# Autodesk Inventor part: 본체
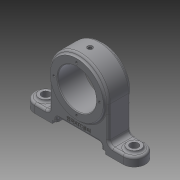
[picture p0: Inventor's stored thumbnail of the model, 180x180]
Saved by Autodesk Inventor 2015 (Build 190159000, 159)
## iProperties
Created: 2019-05
Part Number: 본체
Material: 알루미늄 6061
Document SubType Name: Modeling
Designer: now
Density: 2.7 g/cm^3
Appearance: 기본값
Mass: 456.09 g
Surface Area: 318.797 cm^2
Volume: 168.922 cm^3
Author: now
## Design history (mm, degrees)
sketch "스케치1"
  geometry: L1 (-60, -15)-(60, -15); L2 (60, -15)-(60, 15); L3 (60, 15)-(-60, 15); L4 (-60, 15)-(-60, -15); L5 (-60, -15)-(60, 15); L6 (60, -15)-(-60, 15); 1 further point
  constraints: 12 end point, 2 midpoint, 2 parallel, 1 horizontal, 1 perpendicular
  dimensions: "d0" = 120 distance of L2.end L3.end; "d1" = 30 distance of L1.end L2.end
extrude "돌출1" new body sketch "스케치1" distance "d2" = 12; taper "d3" = 0 deg
sketch "스케치2"
  geometry: L1 (60, -15)-(60, 15) reference; L2 (-60, 15)-(-60, -15) reference; 3 further points
  constraints: 2 midpoint, 2 vertical alignment, 4 other
extrude "돌출2" join sketch "스케치2" distance "d4" = 12; taper "d5" = 0 deg
sketch "스케치3"
  geometry: C1 r 9 at (-60, 0); C2 r 9 at (60, 0); A1 r 15 centre (60, 0) between (60, -15) and (60, 15) reference; A2 r 15 centre (-60, 0) between (-60, 15) and (-60, -15) reference; 1 further point
  constraints: 2 centre point, 2 coincident
  dimensions: "d6" = 18 diameter of C2; "d7" = 18 diameter of C1
extrude "돌출3" join sketch "스케치3" distance "d8" = 3; taper "d9" = 0 deg
sketch "스케치4"
  geometry: C1 r 9 at (0, 0) reference; 1 further point
hole "구멍1" sketch "스케치4" at (0, 0) diameter "d10" = 11; stored, may be unused: countersink angle "d14" = 90 deg, drill point angle "d16" = 118 deg; dims "d11" = 6, "d12" = 4, "d13" = 2, "d15" = 8
sketch "스케치5"
  geometry: L1 (-51, 15)-(-51, 12) reference; L2 (-51, 12)-(51, 12) reference; L3 (51, 12)-(51, 15) reference; L4 (51, 15)-(54.5, 15) reference; L5 (54.5, 15)-(54.5, 0) reference; L6 (54.5, 0)-(-54.5, 0) reference; L7 (-54.5, 0)-(-54.5, 15) reference; L8 (-54.5, 15)-(-51, 15) reference; L9 (75, 12)-(75, 0) reference; L10 (75, 0)-(65.5, 0) reference; L11 (65.5, 0)-(65.5, 15) reference; L12 (65.5, 15)-(69, 15) reference; L13 (69, 15)-(69, 12) reference; L14 (69, 12)-(75, 12) reference; L15 (-75, 0)-(-75, 12) reference; L16 (-75, 12)-(-69, 12) reference; L17 (-69, 12)-(-69, 15) reference; L18 (-69, 15)-(-65.5, 15) reference; L19 (-65.5, 15)-(-65.5, 0) reference; L20 (-65.5, 0)-(-75, 0) reference; L21 (40, 60)-(40, 12); L22 (-40, 60)-(-40, 12); A1 r 40 centre (0, 60) between (40, 60) and (-40, 60); 2 further points
  constraints: 4 end point, 2 point on circle, 2 point on line, 2 tangent, 2 vertical, 1 centre point, 1 midpoint, 1 vertical alignment
  dimensions: "d17" = 80 diameter of A1; "d18" = 60 distance of A1.centre point (0, 0)
extrude "돌출4" join sketch "스케치5" stored distance "d19" = 30; taper "d20" = 0 deg
sketch "스케치6"
  geometry: L1 (0, 0)-(120, 0) reference; L2 (24, 4)-(96, 4); L3 (96, 4)-(96, 0); L4 (96, 0)-(24, 0); L5 (24, 0)-(24, 4); 2 further points
  constraints: 8 end point, 2 midpoint, 2 parallel, 1 horizontal, 1 perpendicular, 1 point on line
  dimensions: "d21" = 4 distance of L2.end L3.end; "d24" = 72 distance between parallel lines of L5 L3
extrude "돌출5" cut sketch "스케치6" stored distance "d25" = 36; taper "d26" = 0 deg
sketch "스케치7"
  geometry: L1 (-96, 4)-(-24, 4) reference; L2 (-90, 10)-(-30, 10); L3 (-30, 10)-(-30, 4); L4 (-30, 4)-(-90, 4); L5 (-90, 4)-(-90, 10); 2 further points
  constraints: 8 end point, 2 midpoint, 2 parallel, 1 horizontal, 1 perpendicular
  dimensions: "d27" = 60 distance of L3.end L4.end; "d28" = 6 distance of L2.end L3.end
extrude "돌출6" cut sketch "스케치7" stored distance "d29" = 36; taper "d30" = 0 deg
sketch "스케치8"
  geometry: A1 r 40 centre (0, 60) between (40, 60) and (-40, 60) reference; 1 further point
hole "구멍2" sketch "스케치8" at (0, 60) diameter "d31" = 52; stored, may be unused: countersink angle "d35" = 90 deg, drill point angle "d37" = 118 deg; dims "d32" = 6, "d33" = 4, "d34" = 2, "d36" = 8
sketch "스케치10"
  geometry: C1 r 26 at (-60, 60) reference; C2 r 36 at (-60, 60); A1 r 40 centre (-60, 60) between (-20, 60) and (-100, 60) reference; 1 further point
  constraints: 1 centre point, 1 coincident
  dimensions: "d38" = 72 diameter of C2
extrude "돌출7" join sketch "스케치10" distance "d39" = 3; taper "d40" = 0 deg
node "작업 평면1"
sketch "스케치11"
  geometry: 1 further point
hole "구멍3" sketch "스케치11" at (0, 0) diameter "d42" = 4.917; stored, may be unused: countersink angle "d46" = 90 deg, drill point angle "d48" = 118 deg; dims "d43" = 8, "d44" = 7, "d45" = 1, "d47" = 10
sketch "스케치12"
  geometry: C1 r 26 at (0, 0) reference; 2 further points
  constraints: 1 vertical alignment
  dimensions: "d49" = 31 distance of point (0, 31) C1.centre
hole "구멍4" sketch "스케치12" at (0, 31) diameter "d50" = 3.242; stored, may be unused: countersink angle "d54" = 90 deg, drill point angle "d56" = 118 deg; dims "d51" = 6, "d52" = 7, "d53" = 1, "d55" = 8
fillet "모깎기1" dims "d60" = 3
sketch "스케치13"
  geometry: C1 r 1.5 at (0, 26); 2 further points
  constraints: 2 vertical alignment, 1 centre point, 1 other
  dimensions: "d61" = 3 diameter of C1
extrude "돌출8" cut sketch "스케치13" stored distance "d62" = 3; taper "d63" = 0 deg
sketch "스케치15"
  geometry: L1 (30, 10)-(90, 10) reference; 2 further points
  constraints: 1 vertical alignment, 1 other
  dimensions: "d73" = 7 distance from line of L1 point (60, 17)
feature "엠보싱1" sketch "스케치15" dims "d74" = 0.5, "d75" = 0
fillet "모깎기9" dims "d76" = 3
fillet "모깎기2" dims "d64" = 6
fillet "모깎기3" dims "d65" = 3
fillet "모깎기4" dims "d66" = 3
fillet "모깎기5" dims "d67" = 3
fillet "모깎기7" dims "d69" = 3
fillet "모깎기8" dims "d70" = 1
node "작업 평면2"
sketch "스케치16"
  geometry: 1 further point
hole "구멍5" sketch "스케치16" at (0, 0) diameter "d78" = 2; stored, may be unused: countersink angle "d82" = 90 deg, drill point angle "d84" = 118 deg; dims "d79" = 6, "d80" = 7, "d81" = 1, "d83" = 8
fillet "모깎기10" dims "d85" = 3
fillet "모깎기11" dims "d86" = 3
node "솔리드1"
mirror "대칭1"
mirror "대칭2"
pattern_circular "원형 패턴1" dims angle "d58" = 360 deg
mirror "대칭3"
node "절단 모서리 투영1"
